Omron CX-Programmer project NuevoProyecto (CX-Programmer 9.50)

# PLC NewPLC1: CP1L-E EM

## Program P16_1 (cyclic task 0)
Local symbols
Etapa_0 10.00 BOOL
Etapa_1 10.01 BOOL
Etapa_10 10.10 BOOL
Etapa_11 10.11 BOOL
Etapa_12 10.12 BOOL
Etapa_13 10.13 BOOL
Etapa_14 10.14 BOOL
Etapa_15 10.15 BOOL
Etapa_16 11.00 BOOL
Etapa_17 11.01 BOOL
Etapa_18 11.02 BOOL
Etapa_19 11.03 BOOL
Etapa_2 10.02 BOOL
Etapa_20 11.04 BOOL
Etapa_21 11.05 BOOL
Etapa_22 11.06 BOOL
Etapa_23 11.07 BOOL
Etapa_3 10.03 BOOL
Etapa_4 10.04 BOOL
Etapa_5 10.05 BOOL
Etapa_6 10.06 BOOL
Etapa_7 10.07 BOOL
Etapa_8 10.08 BOOL
Etapa_9 10.09 BOOL
F1 0.02 BOOL
F2 0.03 BOOL
F3 0.04 BOOL
F4 0.05 BOOL
F5 0.06 BOOL
F6 0.07 BOOL
F7 0.08 BOOL
F8 0.09 BOOL
KB 100.01 BOOL
KD 100.02 BOOL
KI 100.03 BOOL
KS 100.00 BOOL
PD 0.00 BOOL
PI 0.01 BOOL

### Section Sección1_Programa_principal
; Programa principal (Etapas 0 ... 23)

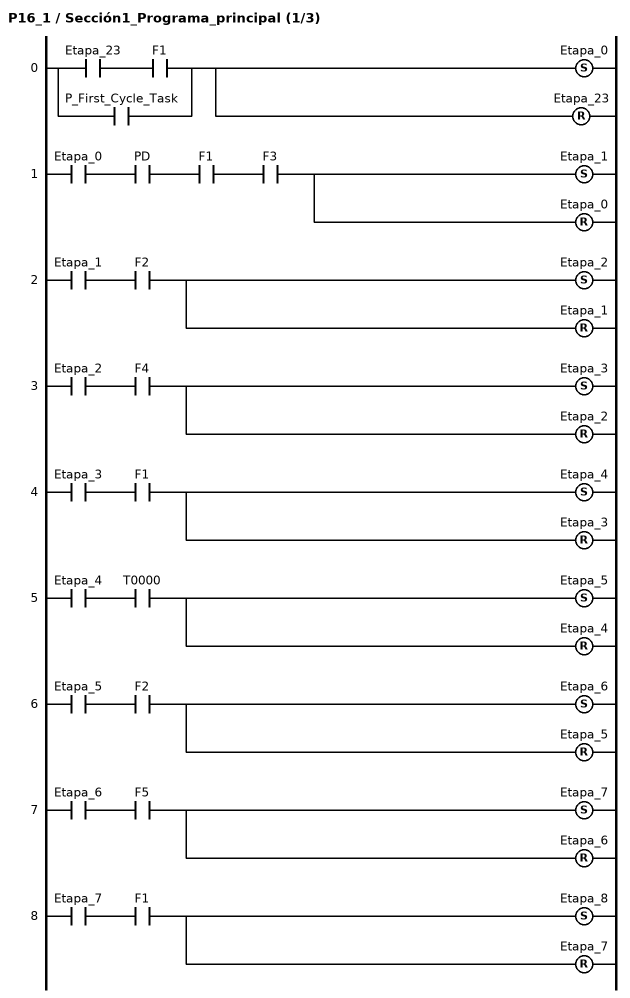
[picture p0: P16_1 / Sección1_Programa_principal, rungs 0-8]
; rung 0
LD Etapa_23
AND F1
OR P_First_Cycle_Task
SET Etapa_0
RSET Etapa_23
; rung 1
LD Etapa_0
AND PD
AND F1
AND F3
SET Etapa_1
RSET Etapa_0
; rung 2
LD Etapa_1
AND F2
SET Etapa_2
RSET Etapa_1
; rung 3
LD Etapa_2
AND F4
SET Etapa_3
RSET Etapa_2
; rung 4
LD Etapa_3
AND F1
SET Etapa_4
RSET Etapa_3
; rung 5
LD Etapa_4
AND T0000
SET Etapa_5
RSET Etapa_4
; rung 6
LD Etapa_5
AND F2
SET Etapa_6
RSET Etapa_5
; rung 7
LD Etapa_6
AND F5
SET Etapa_7
RSET Etapa_6
; rung 8
LD Etapa_7
AND F1
SET Etapa_8
RSET Etapa_7

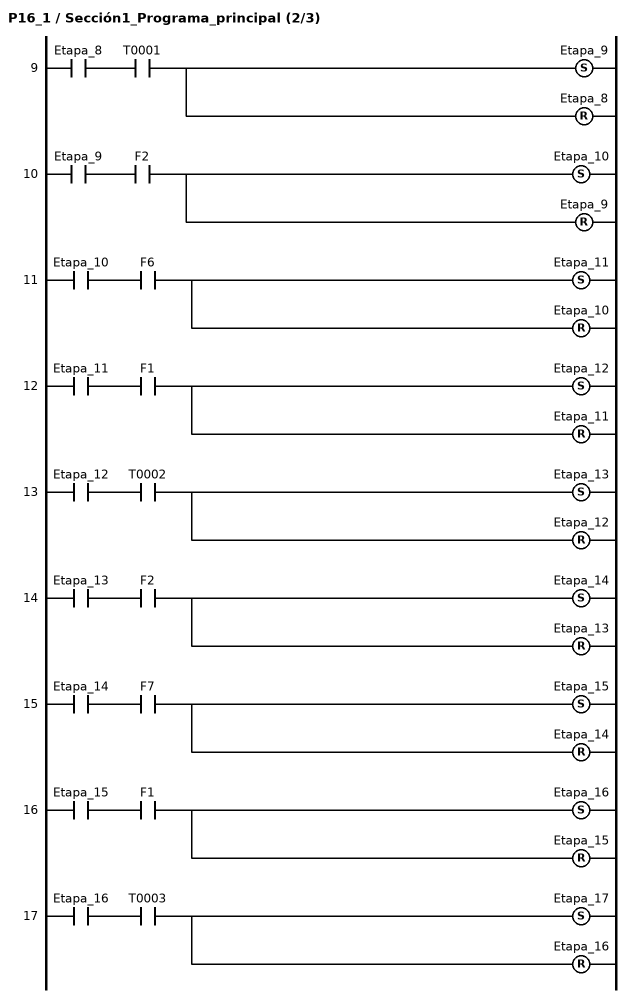
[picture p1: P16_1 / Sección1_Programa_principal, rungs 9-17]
; rung 9
LD Etapa_8
AND T0001
SET Etapa_9
RSET Etapa_8
; rung 10
LD Etapa_9
AND F2
SET Etapa_10
RSET Etapa_9
; rung 11
LD Etapa_10
AND F6
SET Etapa_11
RSET Etapa_10
; rung 12
LD Etapa_11
AND F1
SET Etapa_12
RSET Etapa_11
; rung 13
LD Etapa_12
AND T0002
SET Etapa_13
RSET Etapa_12
; rung 14
LD Etapa_13
AND F2
SET Etapa_14
RSET Etapa_13
; rung 15
LD Etapa_14
AND F7
SET Etapa_15
RSET Etapa_14
; rung 16
LD Etapa_15
AND F1
SET Etapa_16
RSET Etapa_15
; rung 17
LD Etapa_16
AND T0003
SET Etapa_17
RSET Etapa_16

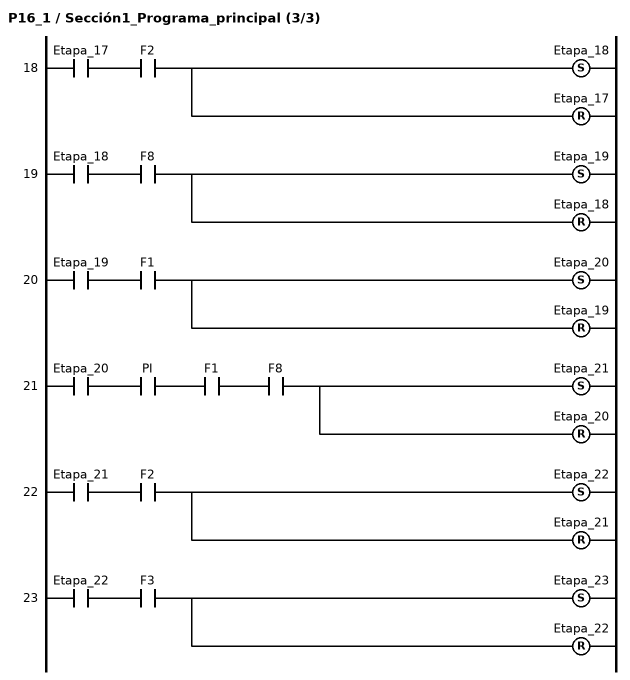
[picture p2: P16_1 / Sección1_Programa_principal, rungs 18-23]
; rung 18
LD Etapa_17
AND F2
SET Etapa_18
RSET Etapa_17
; rung 19
LD Etapa_18
AND F8
SET Etapa_19
RSET Etapa_18
; rung 20
LD Etapa_19
AND F1
SET Etapa_20
RSET Etapa_19
; rung 21
LD Etapa_20
AND PI
AND F1
AND F8
SET Etapa_21
RSET Etapa_20
; rung 22
LD Etapa_21
AND F2
SET Etapa_22
RSET Etapa_21
; rung 23
LD Etapa_22
AND F3
SET Etapa_23
RSET Etapa_22

### Section Sección2_Temporizadores

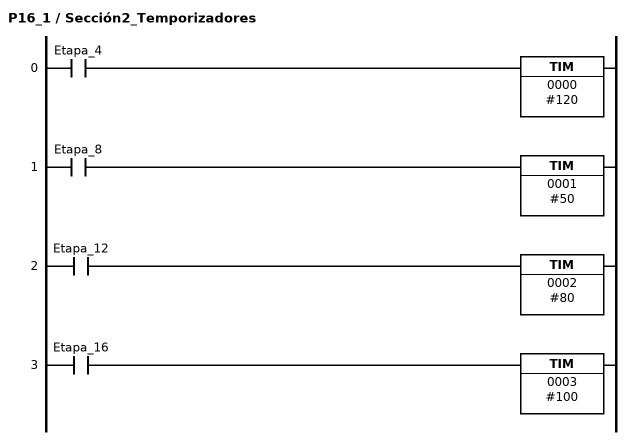
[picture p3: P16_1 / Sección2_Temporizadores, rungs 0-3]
; rung 0
LD Etapa_4
TIM 0000 #120
; rung 1
LD Etapa_8
TIM 0001 #50
; rung 2
LD Etapa_12
TIM 0002 #80
; rung 3
LD Etapa_16
TIM 0003 #100

### Section Sección3_Salidas

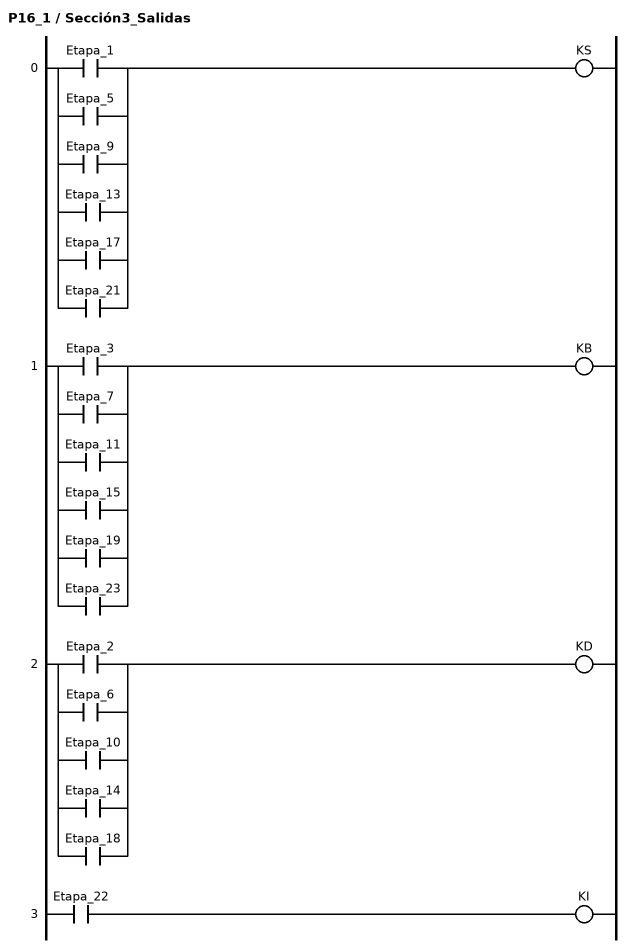
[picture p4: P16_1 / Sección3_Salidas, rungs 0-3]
; rung 0
LD Etapa_1
OR Etapa_5
OR Etapa_9
OR Etapa_13
OR Etapa_17
OR Etapa_21
OUT KS
; rung 1
LD Etapa_3
OR Etapa_7
OR Etapa_11
OR Etapa_15
OR Etapa_19
OR Etapa_23
OUT KB
; rung 2
LD Etapa_2
OR Etapa_6
OR Etapa_10
OR Etapa_14
OR Etapa_18
OUT KD
; rung 3
LD Etapa_22
OUT KI

### Section Sección4_END
; rung 0: Fin de programa
END(001)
